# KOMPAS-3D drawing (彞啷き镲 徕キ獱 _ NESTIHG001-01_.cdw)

Views: Вид 1, Спереди
Referenced files in \\Smallatom\скворечник\: передняя стенка.m3d, Передняя стенка _ NESTIHG001-01.cdw
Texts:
  NESTING001-01
  Передняя стенка
  Лит-Масса-Масштаб
  Материал-Предприятие
  Title Specification
  Body Specification ( left align )
  Body Specificaton ( centered )
  Поз.
  Кол.
  Приме-
  чание
  Таблица спецификации
  Демьянова Л.В.
  NESTIHG001-01-
  КЮТ СО РАН
Dimensions and other numbers on the sheet: 140; 250; 30; 110; 70; 65; 10; 60; 4,2; 4 отв.; 6; 1:2; 1; 0,35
